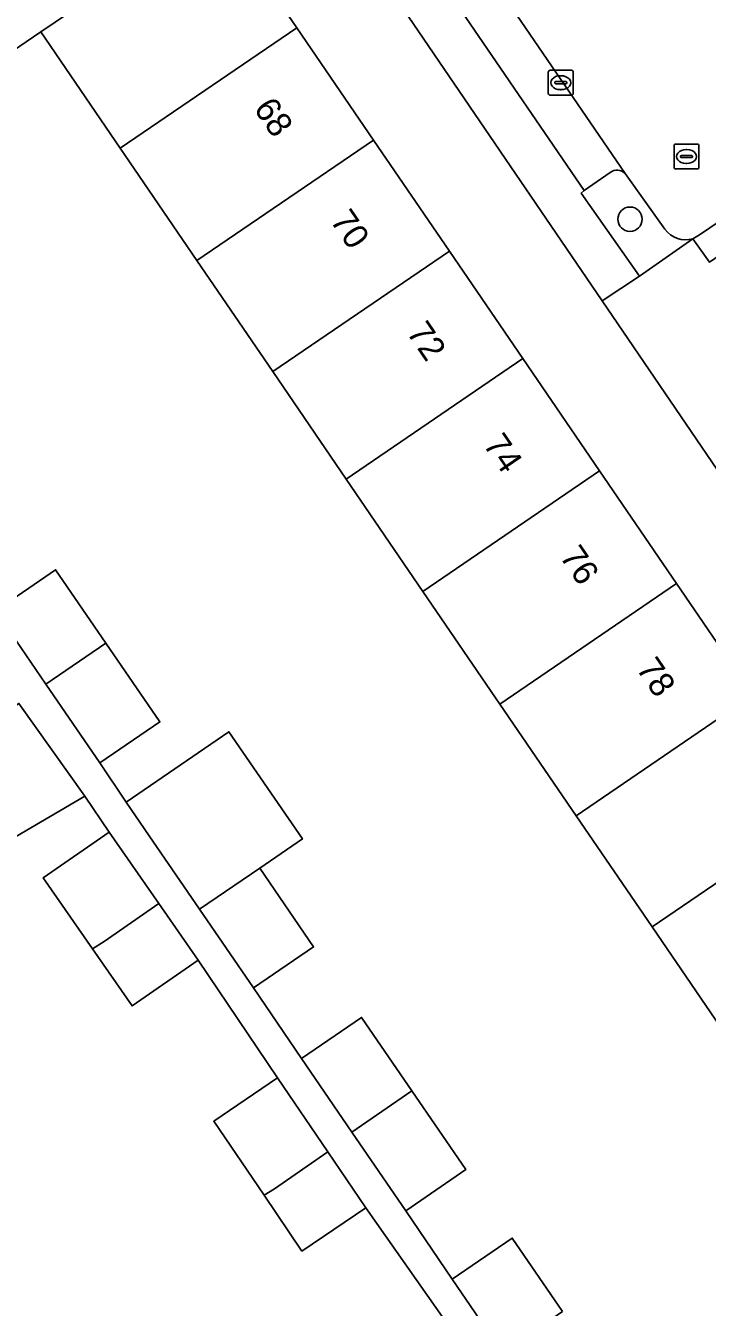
# Model space of a CAD drawing. Extents: x 157445 to 158888, y 383061 to 384688.
# Drawn here: x 158149.9 to 158177.3, y 383626.4 to 383677.9 of the extents above; entities that cross this region are included whole.
import ezdxf

# ---------------------------------------------------------------- set-up
doc = ezdxf.new("R2010")
doc.units = 0
for name, color, linetype in [('IMGEO_Boom', 7, 'Continuous'), ('IMGEO_Erf', 7, 'Continuous'), ('IMGEO_Groenvoorziening', 7, 'Continuous'), ('IMGEO_Kolk', 7, 'Continuous'), ('IMGEO_Pand', 7, 'Continuous'), ('IMGEO_Pand_nummerreeks', 7, 'Continuous'), ('IMGEO_Parkeervlak_open', 7, 'Continuous'), ('IMGEO_Rijbaan_lokaal_open', 7, 'Continuous'), ('IMGEO_Rioolput', 7, 'Continuous'), ('IMGEO_Voetpad_open', 7, 'Continuous')]:
    doc.layers.add(name, color=color, linetype=linetype)

msp = doc.modelspace()

# ---------------------------------------------------------------- linework, layer by layer
at = {"layer": 'IMGEO_Boom'}
msp.add_circle((158174.171, 383670.123), 0.489, dxfattribs=at)
at = {"layer": 'IMGEO_Erf'}
for points in [[(158205.841, 383618.66), (158173.059, 383666.844), (158160.987, 383684.589), (158157.619, 383682.477), (158160.802, 383677.813), (158163.885, 383673.297), (158166.927, 383668.84), (158169.874, 383664.523), (158172.949, 383660.017), (158176.039, 383655.489), (158179.097, 383651.01)], [(158178.188, 383637.124), (158175.062, 383641.704), (158172.013, 383646.171), (158168.956, 383650.65), (158165.865, 383655.177), (158162.79, 383659.684), (158159.842, 383664.002), (158156.801, 383668.458), (158153.718, 383672.974), (158150.533, 383677.641), (158138.495, 383669.426)], [(158148.72, 383654.401), (158151.131, 383656.05), (158153.15, 383653.099), (158155.313, 383649.939), (158152.902, 383648.289), (158153.96, 383646.72), (158158.082, 383649.542), (158161.029, 383645.237), (158159.317, 383644.065), (158161.479, 383640.905), (158159.068, 383639.255), (158160.992, 383636.421), (158163.403, 383638.07), (158165.423, 383635.118), (158167.585, 383631.959), (158165.174, 383630.309), (158167.038, 383627.562), (158169.449, 383629.211), (158171.469, 383626.259)], [(158166.823, 383625.799), (158163.574, 383630.431), (158161.013, 383628.692), (158159.495, 383630.929), (158157.475, 383633.903), (158160.036, 383635.642), (158156.852, 383640.37), (158154.201, 383638.531), (158152.606, 383640.83), (158150.631, 383643.677), (158153.281, 383645.516), (158152.305, 383646.958), (158145.558, 383643.01), (158148.259, 383638.2), (158145.622, 383636.369), (158143.268, 383635.047), (158146.195, 383629.81), (158149.122, 383624.572)]]:
    msp.add_lwpolyline(points, dxfattribs=at)
at = {"layer": 'IMGEO_Groenvoorziening'}
for points in [[(158173.378, 383672.002), (158172.332, 383671.279), (158172.22, 383671.17), (158174.553, 383667.839), (158176.693, 383669.336)], [(158175.575, 383669.718), (158173.981, 383671.962)]]:
    msp.add_lwpolyline(points, dxfattribs=at)
for centre, radius, start, end in [((158173.655, 383671.615), 0.476, 46.7814, 125.6283), ((158176.409, 383670.332), 1.036, 216.3575, 285.9138)]:
    msp.add_arc(centre, radius, start, end, dxfattribs=at)
at = {"layer": 'IMGEO_Kolk'}
for p, q in [((158170.896, 383675.178), (158170.896, 383676.03)), ((158170.971, 383676.104), (158171.823, 383676.104)), ((158171.384, 383675.884), (158171.409, 383675.884)), ((158171.897, 383676.03), (158171.897, 383675.178)), ((158171.155, 383675.598), (158171.155, 383675.61)), ((158171.593, 383675.561), (158171.195, 383675.561)), ((158171.198, 383675.647), (158171.596, 383675.647)), ((158171.407, 383675.324), (158171.382, 383675.324)), ((158171.639, 383675.61), (158171.639, 383675.598)), ((158171.823, 383675.104), (158170.971, 383675.104))]:
    msp.add_line(p, q, dxfattribs=at)
for points in [[(158170.896, 383675.178), (158170.896, 383676.03)], [(158170.971, 383676.104), (158171.823, 383676.104)], [(158171.897, 383676.03), (158171.897, 383675.178)], [(158171.823, 383675.104), (158170.971, 383675.104)]]:
    msp.add_lwpolyline(points, dxfattribs=at)
for centre, radius, start, end in [((158170.973, 383676.028), 0.0765, 91.552, 178.448), ((158170.973, 383676.028), 0.0765, 91.552, 178.448), ((158171.821, 383676.028), 0.0765, 1.552, 88.448), ((158171.821, 383676.028), 0.0765, 1.552, 88.448), ((158171.195, 383675.607), 0.0403, 85.8775, 175.7526), ((158171.192, 383675.597), 0.0366, 178.938, 274.7102), ((158171.596, 383675.604), 0.043, 264.8664, 352.4533), ((158171.6, 383675.609), 0.0386, 1.7309, 96.639), ((158170.973, 383675.18), 0.0765, 181.552, 268.448), ((158170.973, 383675.18), 0.0765, 181.552, 268.448), ((158171.821, 383675.18), 0.0765, 271.552, 358.448), ((158171.821, 383675.18), 0.0765, 271.552, 358.448)]:
    msp.add_arc(centre, radius, start, end, dxfattribs=at)
for centre, major_axis, ratio, start_param, end_param in [((158171.383, 383675.604), (-0.387, 0.002), 0.722429, 4.712389, 7.853982), ((158171.408, 383675.604), (-0.39, 0.002), 0.717154, 1.570796, 4.712389)]:
    msp.add_ellipse(centre, major_axis=major_axis, ratio=ratio, start_param=start_param, end_param=end_param, dxfattribs=at)
at = {"layer": 'IMGEO_Pand'}
for points in [[(158153.718, 383672.974), (158160.802, 383677.813), (158157.619, 383682.477), (158153.49, 383679.659), (158150.533, 383677.641)], [(158156.801, 383668.458), (158163.885, 383673.297), (158160.802, 383677.813), (158153.718, 383672.974)], [(158159.842, 383664.002), (158166.927, 383668.84), (158163.885, 383673.297), (158156.801, 383668.458)], [(158159.842, 383664.002), (158162.79, 383659.684), (158169.874, 383664.523), (158166.927, 383668.84)], [(158172.949, 383660.017), (158169.874, 383664.523), (158162.79, 383659.684), (158165.865, 383655.177)], [(158172.949, 383660.017), (158165.865, 383655.177), (158168.956, 383650.65), (158176.039, 383655.489)], [(158153.15, 383653.099), (158151.131, 383656.05), (158148.72, 383654.401), (158150.738, 383651.451)], [(158179.097, 383651.01), (158176.039, 383655.489), (158168.956, 383650.65), (158172.013, 383646.171)], [(158153.15, 383653.099), (158150.738, 383651.451), (158152.902, 383648.289), (158155.313, 383649.939)], [(158152.305, 383646.958), (158149.655, 383650.681), (158138.232, 383642.552), (158139.853, 383640.208), (158138.405, 383639.399), (158134.04, 383636.959), (158134.161, 383636.742), (158134.454, 383636.906), (158137.349, 383631.725), (158143.268, 383635.047), (158145.622, 383636.369), (158148.259, 383638.2), (158145.558, 383643.01)], [(158182.145, 383646.544), (158179.097, 383651.01), (158172.013, 383646.171), (158175.062, 383641.704)], [(158158.082, 383649.542), (158153.96, 383646.72), (158154.886, 383645.367), (158156.905, 383642.417), (158159.317, 383644.065), (158161.029, 383645.237)], [(158182.145, 383646.544), (158175.062, 383641.704), (158178.188, 383637.124), (158185.272, 383641.963)], [(158155.273, 383642.646), (158153.281, 383645.516), (158150.631, 383643.677), (158152.606, 383640.83), (158153.073, 383641.122)], [(158156.905, 383642.417), (158159.068, 383639.255), (158161.479, 383640.905), (158159.317, 383644.065)], [(158155.273, 383642.646), (158153.073, 383641.122), (158152.606, 383640.83), (158154.201, 383638.531), (158156.852, 383640.37)], [(158163.011, 383633.47), (158165.423, 383635.118), (158163.403, 383638.07), (158160.992, 383636.421)], [(158162.051, 383632.674), (158160.036, 383635.642), (158157.475, 383633.903), (158159.495, 383630.929), (158159.913, 383631.187)], [(158163.011, 383633.47), (158165.174, 383630.309), (158167.585, 383631.959), (158165.423, 383635.118)], [(158162.051, 383632.674), (158159.913, 383631.187), (158159.495, 383630.929), (158161.013, 383628.692), (158163.574, 383630.431)], [(158171.469, 383626.259), (158169.449, 383629.211), (158167.038, 383627.562), (158169.057, 383624.611)]]:
    msp.add_lwpolyline(points, close=True, dxfattribs=at)
at = {"layer": 'IMGEO_Parkeervlak_open'}
for points in [[(158173.981, 383671.962), (158163.526, 383687.266)], [(158163.328, 383686.719), (158162.294, 383685.985), (158172.332, 383671.279), (158173.378, 383672.002)]]:
    msp.add_lwpolyline(points, dxfattribs=at)
msp.add_arc((158173.655, 383671.615), 0.476, 46.7814, 125.6283, dxfattribs=at)
at = {"layer": 'IMGEO_Rijbaan_lokaal_open'}
for points in [[(158159.203, 383701.802), (158155.309, 383699.198), (158155.469, 383698.94), (158157.376, 383696.175), (158161.636, 383690.022), (158163.526, 383687.266), (158173.981, 383671.962), (158175.575, 383669.718)], [(158176.693, 383669.336), (158176.965, 383669.497), (158183.347, 383673.833), (158179.736, 383678.736)]]:
    msp.add_lwpolyline(points, dxfattribs=at)
msp.add_arc((158176.409, 383670.332), 1.036, 216.3575, 285.9138, dxfattribs=at)
at = {"layer": 'IMGEO_Rioolput'}
for p, q in [((158175.939, 383672.213), (158175.939, 383673.065)), ((158176.014, 383673.139), (158176.866, 383673.139)), ((158176.427, 383672.919), (158176.452, 383672.919)), ((158176.94, 383673.065), (158176.94, 383672.213)), ((158176.198, 383672.633), (158176.198, 383672.645)), ((158176.636, 383672.596), (158176.238, 383672.596)), ((158176.241, 383672.682), (158176.639, 383672.682)), ((158176.45, 383672.359), (158176.425, 383672.359)), ((158176.682, 383672.645), (158176.682, 383672.633)), ((158176.866, 383672.139), (158176.014, 383672.139))]:
    msp.add_line(p, q, dxfattribs=at)
for points in [[(158175.939, 383672.213), (158175.939, 383673.065)], [(158176.014, 383673.139), (158176.866, 383673.139)], [(158176.94, 383673.065), (158176.94, 383672.213)], [(158176.866, 383672.139), (158176.014, 383672.139)]]:
    msp.add_lwpolyline(points, dxfattribs=at)
for centre, radius, start, end in [((158176.016, 383673.063), 0.0765, 91.552, 178.448), ((158176.016, 383673.063), 0.0765, 91.552, 178.448), ((158176.864, 383673.063), 0.0765, 1.552, 88.448), ((158176.864, 383673.063), 0.0765, 1.552, 88.448), ((158176.016, 383672.215), 0.0765, 181.552, 268.448), ((158176.016, 383672.215), 0.0765, 181.552, 268.448), ((158176.238, 383672.642), 0.0403, 85.8775, 175.7526), ((158176.235, 383672.632), 0.0366, 178.938, 274.7102), ((158176.639, 383672.639), 0.043, 264.8664, 352.4533), ((158176.643, 383672.644), 0.0386, 1.7309, 96.639), ((158176.864, 383672.215), 0.0765, 271.552, 358.448), ((158176.864, 383672.215), 0.0765, 271.552, 358.448)]:
    msp.add_arc(centre, radius, start, end, dxfattribs=at)
for centre, major_axis, ratio, start_param, end_param in [((158176.426, 383672.639), (-0.387, 0.002), 0.722429, 4.712389, 7.853982), ((158176.451, 383672.639), (-0.39, 0.002), 0.717154, 1.570796, 4.712389)]:
    msp.add_ellipse(centre, major_axis=major_axis, ratio=ratio, start_param=start_param, end_param=end_param, dxfattribs=at)
at = {"layer": 'IMGEO_Voetpad_open'}
for points in [[(158113.107, 383757.926), (158112.77, 383755.176), (158115.18, 383751.638), (158159.53, 383686.796), (158160.987, 383684.589), (158173.059, 383666.844), (158174.553, 383667.839), (158172.22, 383671.17), (158172.332, 383671.279), (158162.294, 383685.985)], [(158169.057, 383624.611), (158167.038, 383627.562), (158165.174, 383630.309), (158163.011, 383633.47), (158160.992, 383636.421), (158159.068, 383639.255), (158156.905, 383642.417), (158154.886, 383645.367), (158153.96, 383646.72), (158152.902, 383648.289), (158150.738, 383651.451), (158148.72, 383654.401), (158146.913, 383657.063), (158144.749, 383660.225), (158142.731, 383663.175), (158142.418, 383663.806), (158141.733, 383664.787), (158138.719, 383669.105), (158138.495, 383669.426), (158150.533, 383677.641), (158153.49, 383679.659)], [(158180.345, 383664.898), (158179.386, 383666.343), (158182.697, 383668.557), (158181.068, 383670.937), (158177.358, 383668.398), (158176.693, 383669.336), (158174.553, 383667.839), (158173.059, 383666.844), (158205.841, 383618.66), (158208.263, 383615.093), (158207.826, 383613.566), (158212.978, 383617.205), (158210.086, 383621.359), (158207.963, 383624.462)], [(158149.655, 383650.681), (158152.305, 383646.958), (158153.281, 383645.516), (158155.273, 383642.646), (158156.852, 383640.37), (158160.036, 383635.642), (158162.051, 383632.674), (158163.574, 383630.431), (158166.823, 383625.799)]]:
    msp.add_lwpolyline(points, dxfattribs=at)
msp.add_lwpolyline([(158183.971, 383672.924), (158183.347, 383673.833), (158176.965, 383669.497), (158176.693, 383669.336), (158177.358, 383668.398), (158181.068, 383670.937)], close=True, dxfattribs=at)

# ---------------------------------------------------------------- texts
at = {"layer": 'IMGEO_Pand_nummerreeks'}
for s, p in [('68', (158159.05, 383674.563)), ('70', (158162.119, 383670.066)), ('72', (158165.185, 383665.574)), ('74', (158168.256, 383661.075)), ('76', (158171.325, 383656.578)), ('78', (158174.396, 383652.079))]:
    msp.add_text(s, height=1, rotation=304.3155, dxfattribs=at).set_placement(p)

doc.saveas('drawing.dxf')
